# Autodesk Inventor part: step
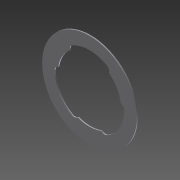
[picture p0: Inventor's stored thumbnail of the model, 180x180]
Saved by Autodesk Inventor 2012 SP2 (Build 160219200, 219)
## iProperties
Created: 2013-12
Part Number: step
Material: Default
Document SubType Name: Modeling
Designer: Alex
Density: 1 g/cm^3
Author: Alex
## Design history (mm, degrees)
sketch "Sketch1"
  geometry: L1 (18.161, -0.051)-(9.525, -0.051); L2 (4.718, 8.274)-(9.036, 15.753); L3 (-9.036, 15.753)-(-4.718, 8.274); L4 (-9.525, -0.051)-(-18.161, -0.051); L5 (-9.124, -15.702)-(-4.806, -8.223); C1 r 28.575 at (0, 0); C2 r 28.575 at (0, 0); A1 r 18.161 centre (0, 0) between (9.036, 15.753) and (-9.036, 15.753); A2 r 18.161 centre (0, 0) between (-18.161, -0.051) and (-9.124, -15.702); A3 r 18.161 centre (0, 0) between (9.124, -15.702) and (18.161, -0.051); A4 r 11.138 centre (0, 0) between (-5.525, 9.671) and (-11.138, -0.051); A5 r 11.138 centre (0, 0) between (11.138, -0.051) and (5.525, 9.671); A6 r 11.138 centre (0, 0) between (-5.613, -9.62) and (5.613, -9.62); A7 r 2.889 centre (9.036, 15.753) between (11.811, 14.947) and (10.474, 18.259); A8 r 2.889 centre (-9.036, 15.753) between (-10.474, 18.259) and (-11.811, 14.947); A9 r 2.889 centre (-18.161, -0.051) between (-21.049, 0.032) and (-21.05, -0.059); A10 r 2.889 centre (-18.161, -0.051) between (-18.85, 2.755) and (-21.05, -0.059); A11 r 2.889 centre (18.161, -0.051) between (21.05, -0.059) and (18.85, 2.755); A12 r 2.889 centre (9.124, -15.702) between (7.039, -17.702) and (10.576, -18.201); A13 r 2.889 centre (-9.124, -15.702) between (-10.576, -18.201) and (-7.039, -17.702); A14 r 19.05 centre (0, 0) between (18.85, 2.755) and (11.811, 14.947); A15 r 21.05 centre (0, 0) between (-21.05, -0.059) and (-10.576, -18.201); A16 r 21.05 centre (0, 0) between (10.576, -18.201) and (21.05, -0.059); A17 r 21.05 centre (0, 0) between (10.474, 18.259) and (-10.474, 18.259); A18 r 19.05 centre (0, 0) between (-11.811, 14.947) and (-18.85, 2.755); A19 r 19.05 centre (0, 0) between (-7.039, -17.702) and (7.039, -17.702); 1 further point
  constraints: 38 point on circle, 21 centre point, 14 coincident, 10 end point, 6 tangent, 1 concentric
  dimensions: "d0" = 57.15 diameter of C2 (derived); "d1" = 11.1379 radius of A4 (derived); "d2" = 18.161 radius of A2 (derived); "d3" = 19.05 radius of A18 (computed from d2); "d4" = 19.05 radius of A14 (= d3); "d5" = 19.05 radius of A19 (= d3); "d6" = 21.05025 radius of A17 (computed from d2); "d7" = 21.05025 radius of A15 (= d6); "d8" = 21.05025 radius of A16 (= d6)
extrude "Extrusion1" new body sketch "Sketch1" distance "d9" = 0.6604; taper "d10" = 0 deg
body "Solid1"
